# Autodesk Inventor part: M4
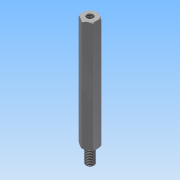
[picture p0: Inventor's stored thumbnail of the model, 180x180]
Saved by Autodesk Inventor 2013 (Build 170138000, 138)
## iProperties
Created: 2012-08
Part Number: M4
Material: Stahl
Document SubType Name: Modeling
Designer: rYan
Density: 7.85 g/cm^3
Mass: 18.4933 g
Surface Area: 16.0447 cm^2
Volume: 2.35583 cm^3
Author: rYan
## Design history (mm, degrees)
derived "Abstandsbolzen Typ B.ipt"
feature "Volumenkörper1::Abstandsbolzen Typ B.ipt"
tag "Bezeichnung1"
node "Volumenkörper1"
other parameters: "SW" = 7, "L" = 55, "d2" = 0, "l_" = 9, "d9" = 118 deg, "GA_" = 4, "A_" = 8, "d13" = 0, "d17" = 0.25, "d20" = 45 deg
